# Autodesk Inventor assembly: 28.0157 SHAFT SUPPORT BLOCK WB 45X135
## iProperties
Created: 2007-06
Part Number: 28.0157 SHAFT SUPPORT BLOCK WB 45X135
Document SubType Name: Assembly
Designer: Andy Moles
Author: Andy Moles
